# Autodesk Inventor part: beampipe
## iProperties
Shininess: 64.0
Length Units: 11269
Angle Units: 11279
Time Units: 11290
Mass Units: 11283
Length Display Precision: 3
Angle Display Precision: 2
Compacted: True
Part Number: beampipe
Document SubType Name: Modeling
Created: 2004-07
Designer: Peter
Manufacturer: Standard
Standards Organization: Custom
Density: 0.0
Volumn: 0.0
Area: 0.0
PropertySet Name: Model Information
Control State: 0
Master: False
Checked Out: False
Author: Peter
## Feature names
1. Revolution1
2. Extrusion1
